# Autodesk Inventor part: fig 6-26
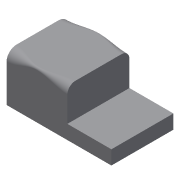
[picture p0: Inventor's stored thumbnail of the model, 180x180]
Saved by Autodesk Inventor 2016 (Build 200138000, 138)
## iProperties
Created: 2004-05
Part Number: fig 6-26
Document SubType Name: Modeling
Designer: CADCIM Technologies
Manufacturer: Standard
Standards Organization: Custom
Density: 1 g/cm^3
Material: Generic
Appearance: Default
Author: CADCIM Technologies
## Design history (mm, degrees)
node "Sketch1"
sketch "Sketch2"
  geometry: L1 (0.098, 47.711)-(0.098, 0.049); L2 (0.098, 0.049)-(-105.483, 0.049); L3 (-105.483, 0.049)-(-105.483, 14.192); L4 (-105.483, 14.192)-(-61.139, 14.192); L5 (-61.139, 14.192)-(-61.139, 47.711); L6 (-61.139, 47.711)-(0.098, 47.711)
  constraints: 12 end point, 3 parallel, 2 perpendicular, 1 vertical
extrude "Extrusion1" new body sketch "Sketch2" stored distance "d0" = 62.5; taper "d1" = 0 deg
fillet "Fillet9" dims "d61" = 10, "d62" = 8, "d63" = 2, "d64" = 5
fillet "Fillet10" dims "d65" = 8, "d66" = 10, "d67" = 2, "d68" = 5
body "Solid1"
